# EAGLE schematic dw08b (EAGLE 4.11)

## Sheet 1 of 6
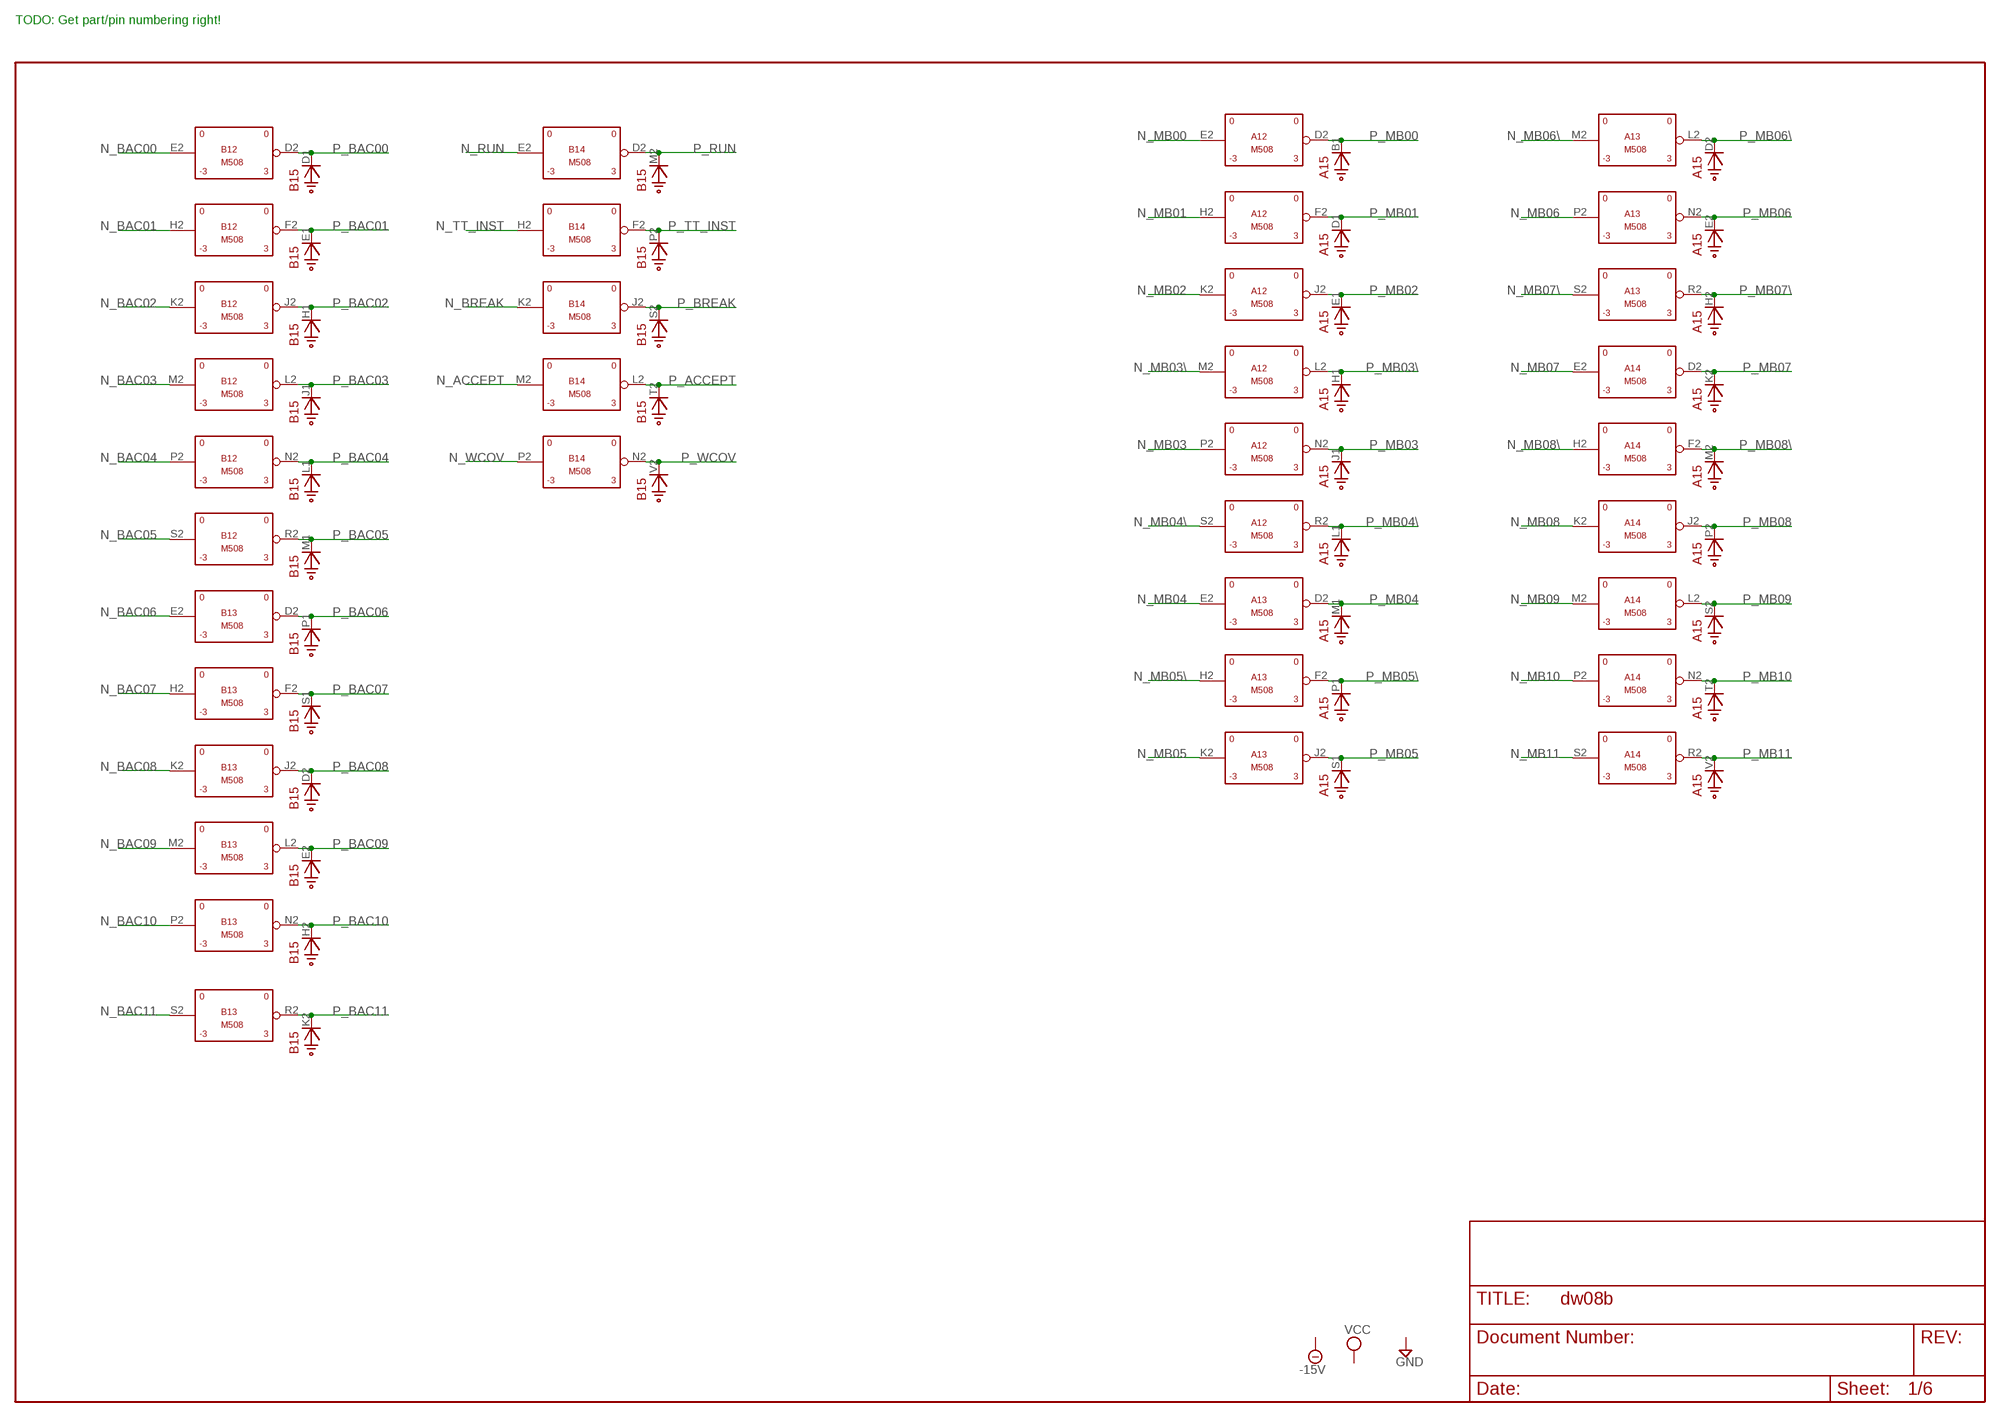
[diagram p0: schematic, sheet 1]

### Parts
A12  M508  [H807]
A13  M508  [H807]
A14  M508  [H807]
A15  M906  [H807]
B12  M508  [H807]
B13  M508  [H807]
B14  M508  [H807]
B15  M906  [H807]

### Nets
N_ACCEPT: B14.M2(IN) ; also sheet 5
N_BAC00: B12.E2(IN) ; also sheet 5
N_BAC01: B12.H2(IN) ; also sheet 5
N_BAC02: B12.K2(IN) ; also sheet 5
N_BAC03: B12.M2(IN) ; also sheet 5
N_BAC04: B12.P2(IN) ; also sheet 5
N_BAC05: B12.S2(IN) ; also sheet 5
N_BAC06: B13.E2(IN) ; also sheet 5
N_BAC07: B13.H2(IN) ; also sheet 5
N_BAC08: B13.K2(IN) ; also sheet 5
N_BAC09: B13.M2(IN) ; also sheet 5
N_BAC10: B13.P2(IN) ; also sheet 5
N_BAC11: B13.S2(IN) ; also sheet 5
N_BREAK: B14.K2(IN) ; also sheet 5
N_MB00: A12.E2(IN) ; also sheet 5
N_MB01: A12.H2(IN) ; also sheet 5
N_MB02: A12.K2(IN) ; also sheet 5
N_MB03: A12.P2(IN) ; also sheet 5
N_MB03\: A12.M2(IN) ; also sheet 5
N_MB04: A13.E2(IN) ; also sheet 5
N_MB04\: A12.S2(IN) ; also sheet 5
N_MB05: A13.K2(IN) ; also sheet 5
N_MB05\: A13.H2(IN) ; also sheet 5
N_MB06: A13.P2(IN) ; also sheet 5
N_MB06\: A13.M2(IN) ; also sheet 5
N_MB07: A14.E2(IN) ; also sheet 5
N_MB07\: A13.S2(IN) ; also sheet 5
N_MB08: A14.K2(IN) ; also sheet 5
N_MB08\: A14.H2(IN) ; also sheet 5
N_MB09: A14.M2(IN) ; also sheet 5
N_MB10: A14.P2(IN) ; also sheet 5
N_MB11: A14.S2(IN) ; also sheet 5
N_RUN: B14.E2(IN) ; also sheet 5
N_TT_INST: B14.H2(IN) ; also sheet 5
N_WCOV: B14.P2(IN) ; also sheet 5
P_ACCEPT: B14.L2(OUT) B15.T2(CATHODE) ; also sheet 6
P_BAC00: B12.D2(OUT) B15.D1(CATHODE) ; also sheet 6
P_BAC01: B12.F2(OUT) B15.E1(CATHODE) ; also sheet 6
P_BAC02: B12.J2(OUT) B15.H1(CATHODE) ; also sheet 6
P_BAC03: B12.L2(OUT) B15.J1(CATHODE) ; also sheet 6
P_BAC04: B12.N2(OUT) B15.L1(CATHODE) ; also sheet 6
P_BAC05: B12.R2(OUT) B15.M1(CATHODE) ; also sheet 6
P_BAC06: B13.D2(OUT) B15.P1(CATHODE) ; also sheet 6
P_BAC07: B13.F2(OUT) B15.S1(CATHODE) ; also sheet 6
P_BAC08: B13.J2(OUT) B15.D2(CATHODE) ; also sheet 6
P_BAC09: B13.L2(OUT) B15.E2(CATHODE) ; also sheet 6
P_BAC10: B13.N2(OUT) B15.H2(CATHODE) ; also sheet 6
P_BAC11: B13.R2(OUT) B15.K2(CATHODE) ; also sheet 6
P_BREAK: B14.J2(OUT) B15.S2(CATHODE) ; also sheet 6
P_MB00: A12.D2(OUT) A15.B1(CATHODE) ; also sheet 6
P_MB01: A12.F2(OUT) A15.D1(CATHODE) ; also sheet 6
P_MB02: A12.J2(OUT) A15.E1(CATHODE) ; also sheet 6
P_MB03: A12.N2(OUT) A15.J1(CATHODE) ; also sheet 6
P_MB03\: A12.L2(OUT) A15.H1(CATHODE) ; also sheet 6
P_MB04: A13.D2(OUT) A15.M1(CATHODE) ; also sheet 6
P_MB04\: A12.R2(OUT) A15.L1(CATHODE) ; also sheet 6
P_MB05: A13.J2(OUT) A15.S1(CATHODE) ; also sheet 6
P_MB05\: A13.F2(OUT) A15.P1(CATHODE) ; also sheet 6
P_MB06: A13.N2(OUT) A15.E2(CATHODE) ; also sheet 6
P_MB06\: A13.L2(OUT) A15.D2(CATHODE) ; also sheet 6
P_MB07: A14.D2(OUT) A15.K2(CATHODE) ; also sheet 6
P_MB07\: A13.R2(OUT) A15.H2(CATHODE) ; also sheet 6
P_MB08: A14.J2(OUT) A15.P2(CATHODE) ; also sheet 6
P_MB08\: A14.F2(OUT) A15.M2(CATHODE) ; also sheet 6
P_MB09: A14.L2(OUT) A15.S2(CATHODE) ; also sheet 6
P_MB10: A14.N2(OUT) A15.T2(CATHODE) ; also sheet 6
P_MB11: A14.R2(OUT) A15.V2(CATHODE) ; also sheet 6
P_RUN: B14.D2(OUT) B15.M2(CATHODE) ; also sheet 6
P_TT_INST: B14.F2(OUT) B15.P2(CATHODE) ; also sheet 6
P_WCOV: B14.N2(OUT) B15.V2(CATHODE) ; also sheet 6
Unconnected: B14.R2(OUT) B14.S2(IN)

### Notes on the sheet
- TODO: Get part/pin numbering right!

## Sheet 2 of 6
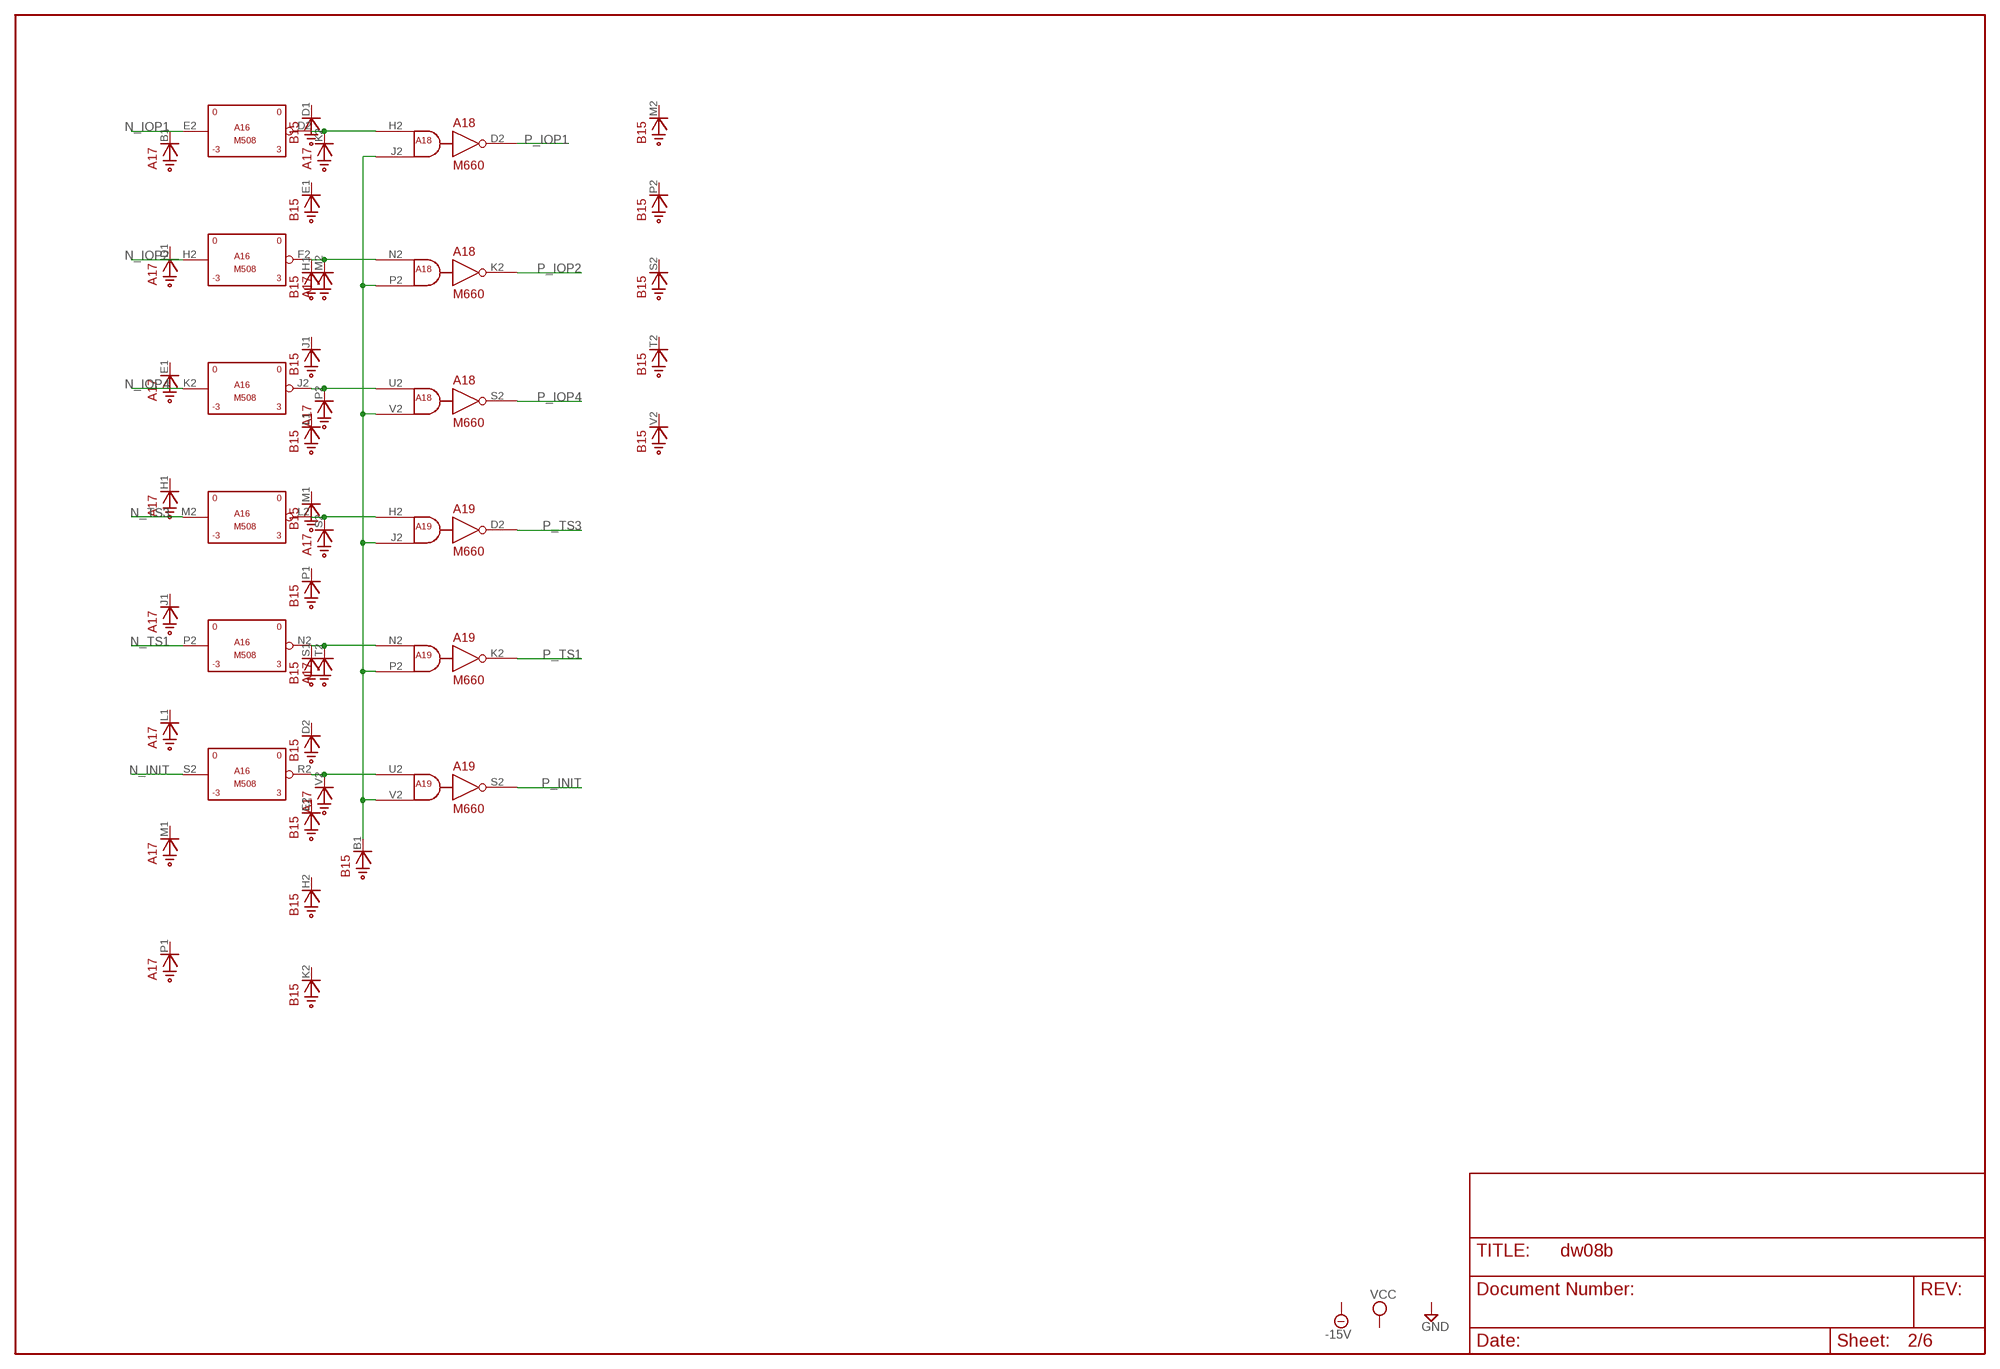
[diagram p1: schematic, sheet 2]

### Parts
A16  M508  [H807]
A17  M906  [H807]
A18  M660  [H807]
A19  M660  [H807]

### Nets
N$1: A16.D2(OUT) A17.K2(CATHODE) A18.H2(IN1)
N$2: A16.F2(OUT) A17.M2(CATHODE) A18.N2(IN1)
N$3: A16.J2(OUT) A17.P2(CATHODE) A18.U2(IN1)
N$4: A16.L2(OUT) A17.S2(CATHODE) A19.H2(IN1)
N$5: A16.N2(OUT) A17.T2(CATHODE) A19.N2(IN1)
N$6: A16.R2(OUT) A17.V2(CATHODE) A19.U2(IN1)
N$7: A18.J2(IN2) A18.P2(IN2) A18.V2(IN2) A19.J2(IN2) A19.P2(IN2) A19.V2(IN2) B15.B1(CATHODE)
N_INIT: A16.S2(IN) ; also sheet 5
N_IOP1: A16.E2(IN) ; also sheet 5
N_IOP2: A16.H2(IN) ; also sheet 5
N_IOP4: A16.K2(IN) ; also sheet 5
N_TS1: A16.P2(IN) ; also sheet 5
N_TS3: A16.M2(IN) ; also sheet 5
P_INIT: A19.S2(OUT) ; also sheet 6
P_IOP1: A18.D2(OUT) ; also sheet 6
P_IOP2: A18.K2(OUT) ; also sheet 6
P_IOP4: A18.S2(OUT) ; also sheet 6
P_TS1: A19.K2(OUT) ; also sheet 6
P_TS3: A19.D2(OUT) ; also sheet 6

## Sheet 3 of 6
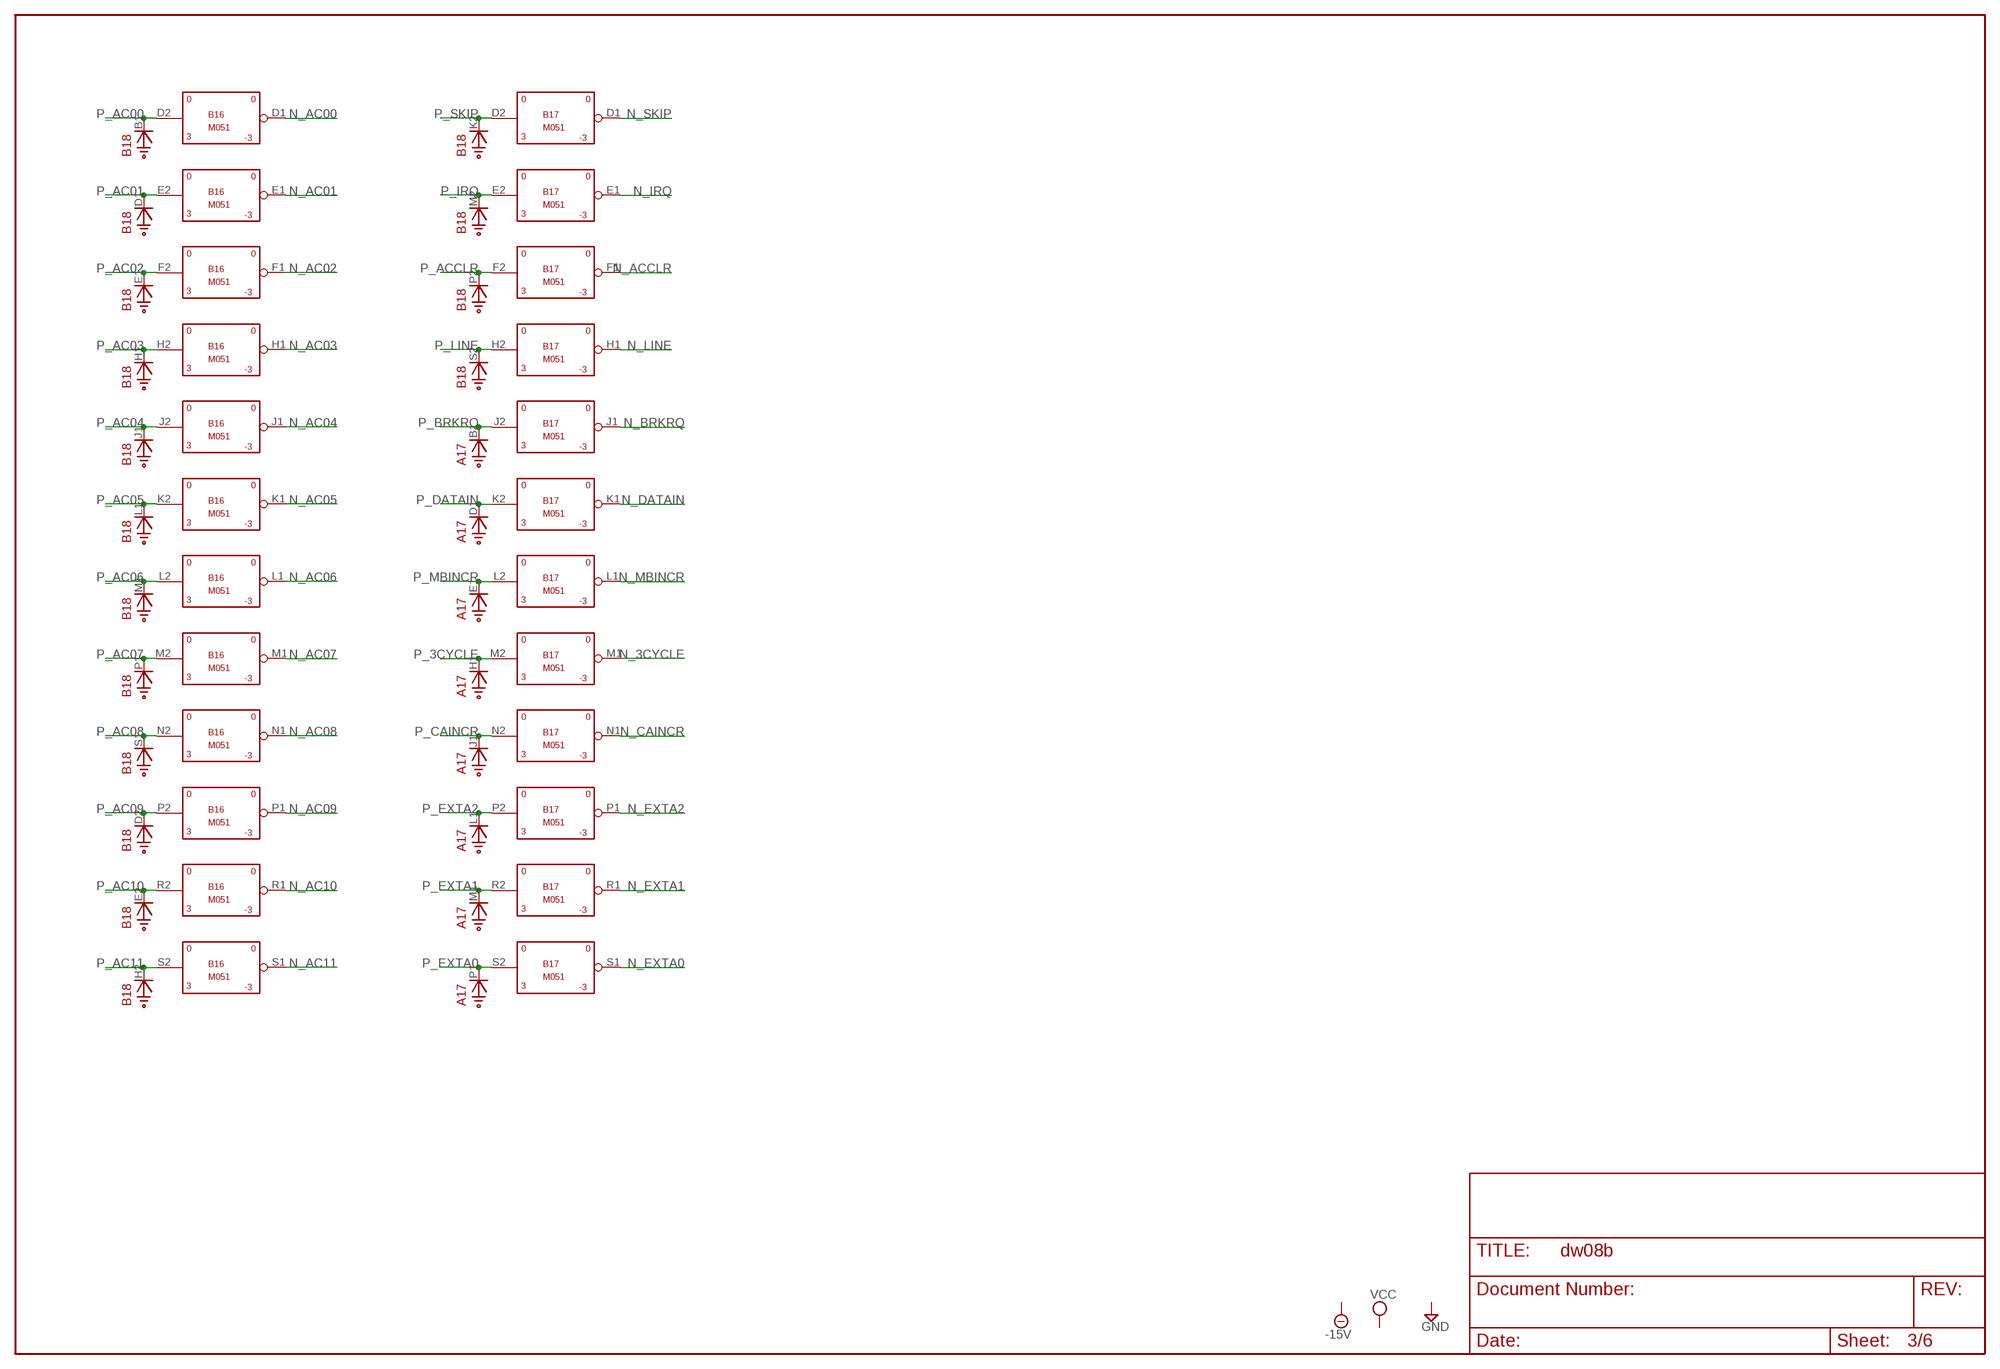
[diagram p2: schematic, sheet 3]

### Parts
B16  M051  [H807]
B17  M051  [H807]
B18  M906  [H807]

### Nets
N_3CYCLE: B17.M1(OUT) ; also sheet 5
N_AC00: B16.D1(OUT) ; also sheet 5
N_AC01: B16.E1(OUT) ; also sheet 5
N_AC02: B16.F1(OUT) ; also sheet 5
N_AC03: B16.H1(OUT) ; also sheet 5
N_AC04: B16.J1(OUT) ; also sheet 5
N_AC05: B16.K1(OUT) ; also sheet 5
N_AC06: B16.L1(OUT) ; also sheet 5
N_AC07: B16.M1(OUT) ; also sheet 5
N_AC08: B16.N1(OUT) ; also sheet 5
N_AC09: B16.P1(OUT) ; also sheet 5
N_AC10: B16.R1(OUT) ; also sheet 5
N_AC11: B16.S1(OUT) ; also sheet 5
N_ACCLR: B17.F1(OUT) ; also sheet 5
N_BRKRQ: B17.J1(OUT) ; also sheet 5
N_CAINCR: B17.N1(OUT) ; also sheet 5
N_DATAIN: B17.K1(OUT) ; also sheet 5
N_EXTA0: B17.S1(OUT) ; also sheet 5
N_EXTA1: B17.R1(OUT) ; also sheet 5
N_EXTA2: B17.P1(OUT) ; also sheet 5
N_IRQ: B17.E1(OUT) ; also sheet 5
N_LINE: B17.H1(OUT) ; also sheet 5
N_MBINCR: B17.L1(OUT) ; also sheet 5
N_SKIP: B17.D1(OUT) ; also sheet 5
P_3CYCLE: A17.H1(CATHODE) B17.M2(IN) ; also sheet 6
P_AC00: B16.D2(IN) B18.B1(CATHODE) ; also sheet 6
P_AC01: B16.E2(IN) B18.D1(CATHODE) ; also sheet 6
P_AC02: B16.F2(IN) B18.E1(CATHODE) ; also sheet 6
P_AC03: B16.H2(IN) B18.H1(CATHODE) ; also sheet 6
P_AC04: B16.J2(IN) B18.J1(CATHODE) ; also sheet 6
P_AC05: B16.K2(IN) B18.L1(CATHODE) ; also sheet 6
P_AC06: B16.L2(IN) B18.M1(CATHODE) ; also sheet 6
P_AC07: B16.M2(IN) B18.P1(CATHODE) ; also sheet 6
P_AC08: B16.N2(IN) B18.S1(CATHODE) ; also sheet 6
P_AC09: B16.P2(IN) B18.D2(CATHODE) ; also sheet 6
P_AC10: B16.R2(IN) B18.E2(CATHODE) ; also sheet 6
P_AC11: B16.S2(IN) B18.H2(CATHODE) ; also sheet 6
P_ACCLR: B17.F2(IN) B18.P2(CATHODE) ; also sheet 6
P_BRKRQ: A17.B1(CATHODE) B17.J2(IN) ; also sheet 6
P_CAINCR: A17.J1(CATHODE) B17.N2(IN) ; also sheet 6
P_DATAIN: A17.D1(CATHODE) B17.K2(IN) ; also sheet 6
P_EXTA0: A17.P1(CATHODE) B17.S2(IN) ; also sheet 6
P_EXTA1: A17.M1(CATHODE) B17.R2(IN) ; also sheet 6
P_EXTA2: A17.L1(CATHODE) B17.P2(IN) ; also sheet 6
P_IRQ: B17.E2(IN) B18.M2(CATHODE) ; also sheet 6
P_LINE: B17.H2(IN) B18.S2(CATHODE) ; also sheet 6
P_MBINCR: A17.E1(CATHODE) B17.L2(IN) ; also sheet 6
P_SKIP: B17.D2(IN) B18.K2(CATHODE) ; also sheet 6

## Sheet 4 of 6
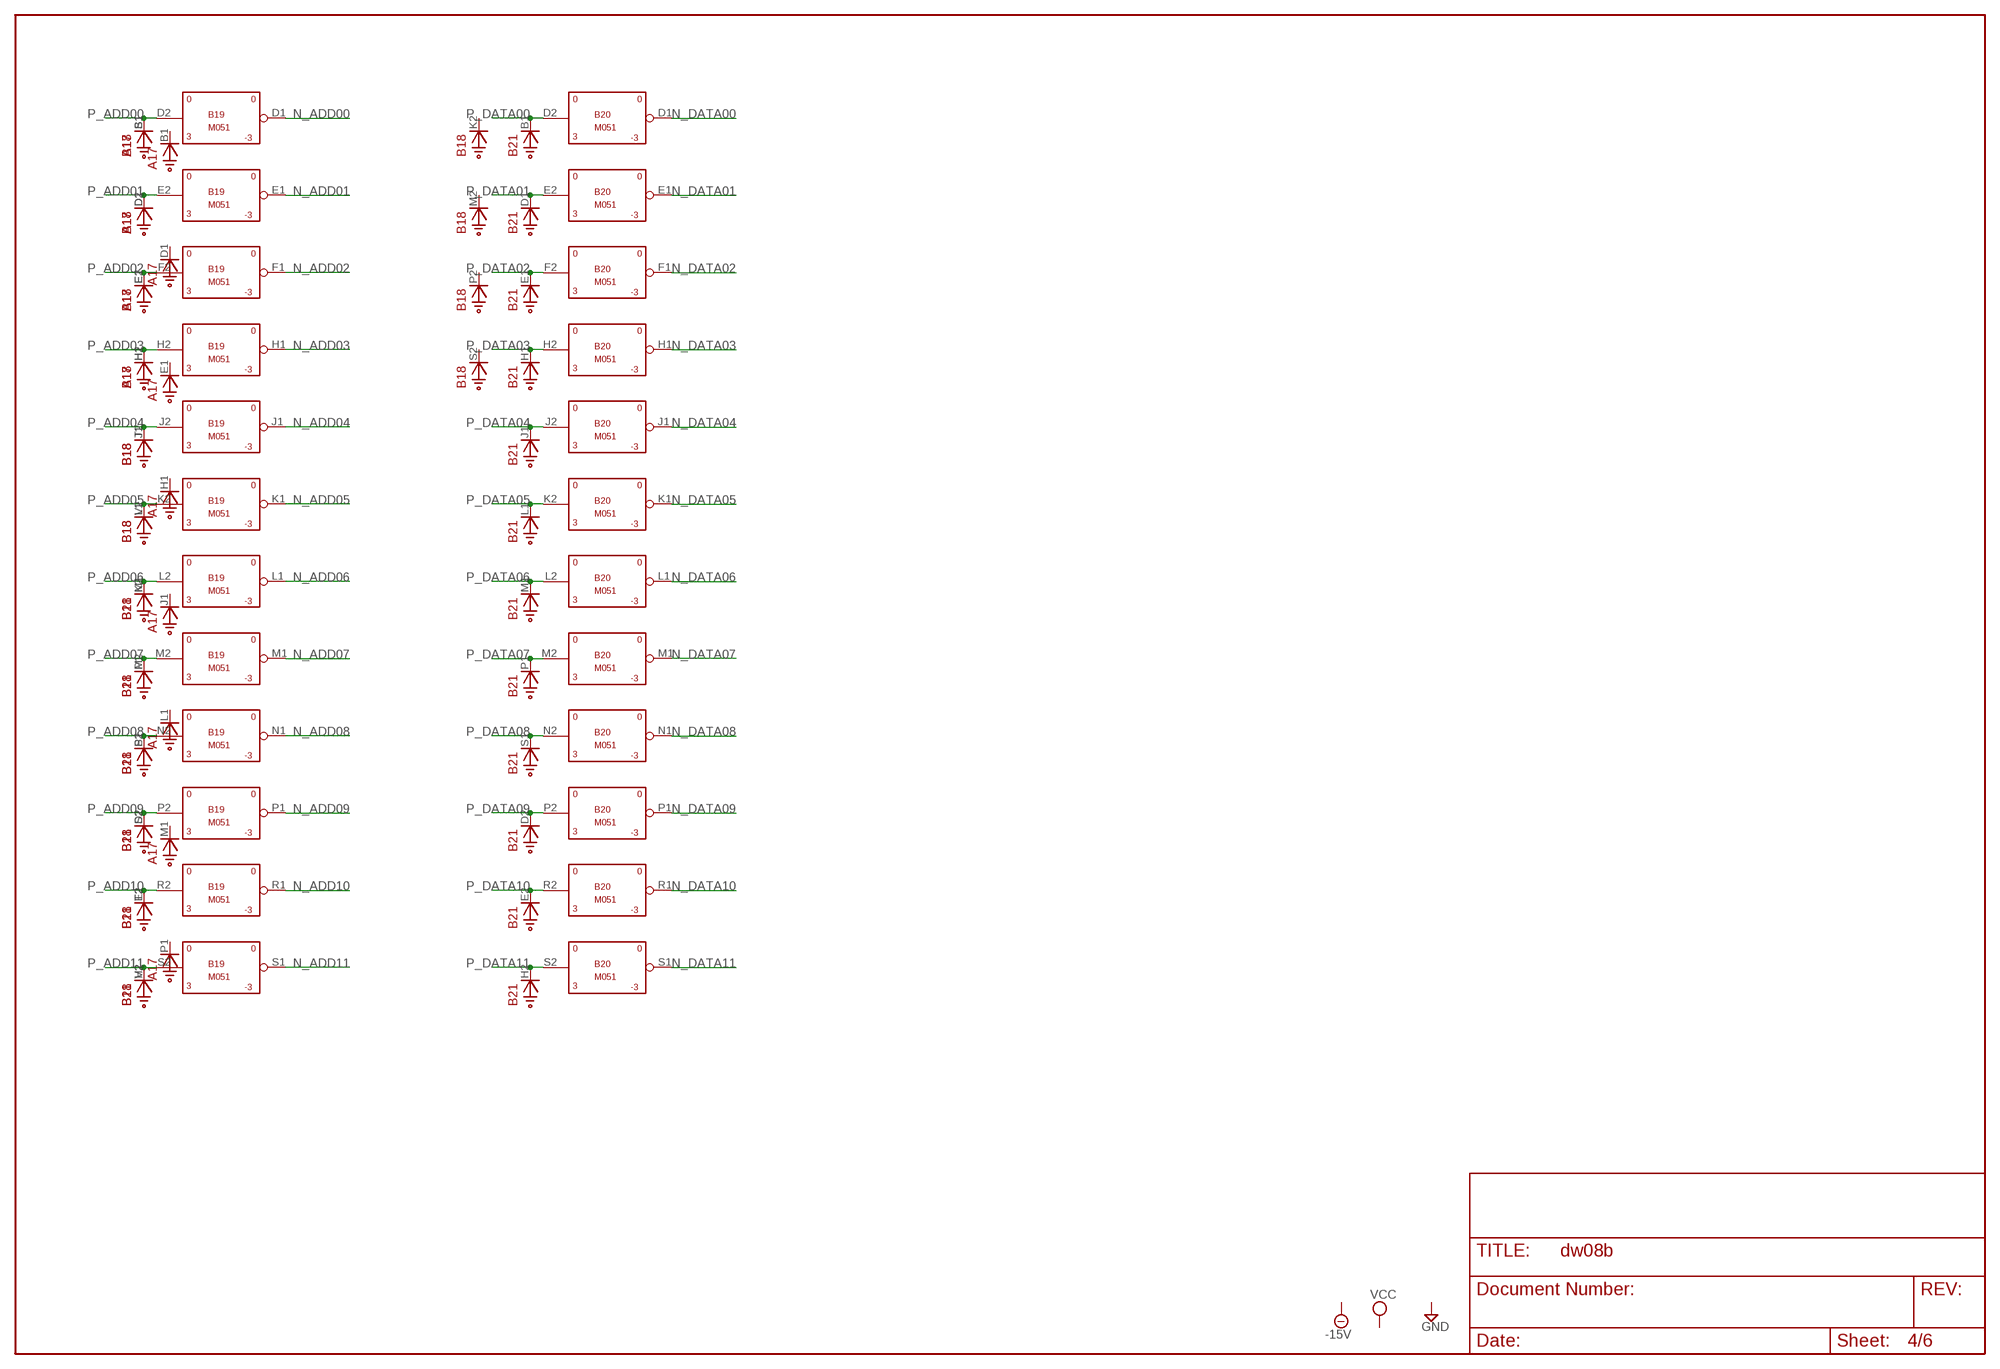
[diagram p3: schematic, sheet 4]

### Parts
B19  M051  [H807]
B20  M051  [H807]
B21  M906  [H807]

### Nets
N_ADD00: B19.D1(OUT) ; also sheet 5
N_ADD01: B19.E1(OUT) ; also sheet 5
N_ADD02: B19.F1(OUT) ; also sheet 5
N_ADD03: B19.H1(OUT) ; also sheet 5
N_ADD04: B19.J1(OUT) ; also sheet 5
N_ADD05: B19.K1(OUT) ; also sheet 5
N_ADD06: B19.L1(OUT) ; also sheet 5
N_ADD07: B19.M1(OUT) ; also sheet 5
N_ADD08: B19.N1(OUT) ; also sheet 5
N_ADD09: B19.P1(OUT) ; also sheet 5
N_ADD10: B19.R1(OUT) ; also sheet 5
N_ADD11: B19.S1(OUT) ; also sheet 5
N_DATA00: B20.D1(OUT) ; also sheet 5
N_DATA01: B20.E1(OUT) ; also sheet 5
N_DATA02: B20.F1(OUT) ; also sheet 5
N_DATA03: B20.H1(OUT) ; also sheet 5
N_DATA04: B20.J1(OUT) ; also sheet 5
N_DATA05: B20.K1(OUT) ; also sheet 5
N_DATA06: B20.L1(OUT) ; also sheet 5
N_DATA07: B20.M1(OUT) ; also sheet 5
N_DATA08: B20.N1(OUT) ; also sheet 5
N_DATA09: B20.P1(OUT) ; also sheet 5
N_DATA10: B20.R1(OUT) ; also sheet 5
N_DATA11: B20.S1(OUT) ; also sheet 5
P_ADD00: A17.S1(CATHODE) B19.D2(IN) ; also sheet 6
P_ADD01: A17.D2(CATHODE) B19.E2(IN) ; also sheet 6
P_ADD02: A17.E2(CATHODE) B19.F2(IN) ; also sheet 6
P_ADD03: A17.H2(CATHODE) B19.H2(IN) ; also sheet 6
P_ADD04: B18.T2(CATHODE) B19.J2(IN) ; also sheet 6
P_ADD05: B18.V2(CATHODE) B19.K2(IN) ; also sheet 6
P_ADD06: B19.L2(IN) B21.K2(CATHODE) ; also sheet 6
P_ADD07: B19.M2(IN) B21.M2(CATHODE) ; also sheet 6
P_ADD08: B19.N2(IN) B21.P2(CATHODE) ; also sheet 6
P_ADD09: B19.P2(IN) B21.S2(CATHODE) ; also sheet 6
P_ADD10: B19.R2(IN) B21.T2(CATHODE) ; also sheet 6
P_ADD11: B19.S2(IN) B21.V2(CATHODE) ; also sheet 6
P_DATA00: B20.D2(IN) B21.B1(CATHODE) ; also sheet 6
P_DATA01: B20.E2(IN) B21.D1(CATHODE) ; also sheet 6
P_DATA02: B20.F2(IN) B21.E1(CATHODE) ; also sheet 6
P_DATA03: B20.H2(IN) B21.H1(CATHODE) ; also sheet 6
P_DATA04: B20.J2(IN) B21.J1(CATHODE) ; also sheet 6
P_DATA05: B20.K2(IN) B21.L1(CATHODE) ; also sheet 6
P_DATA06: B20.L2(IN) B21.M1(CATHODE) ; also sheet 6
P_DATA07: B20.M2(IN) B21.P1(CATHODE) ; also sheet 6
P_DATA08: B20.N2(IN) B21.S1(CATHODE) ; also sheet 6
P_DATA09: B20.P2(IN) B21.D2(CATHODE) ; also sheet 6
P_DATA10: B20.R2(IN) B21.E2(CATHODE) ; also sheet 6
P_DATA11: B20.S2(IN) B21.H2(CATHODE) ; also sheet 6

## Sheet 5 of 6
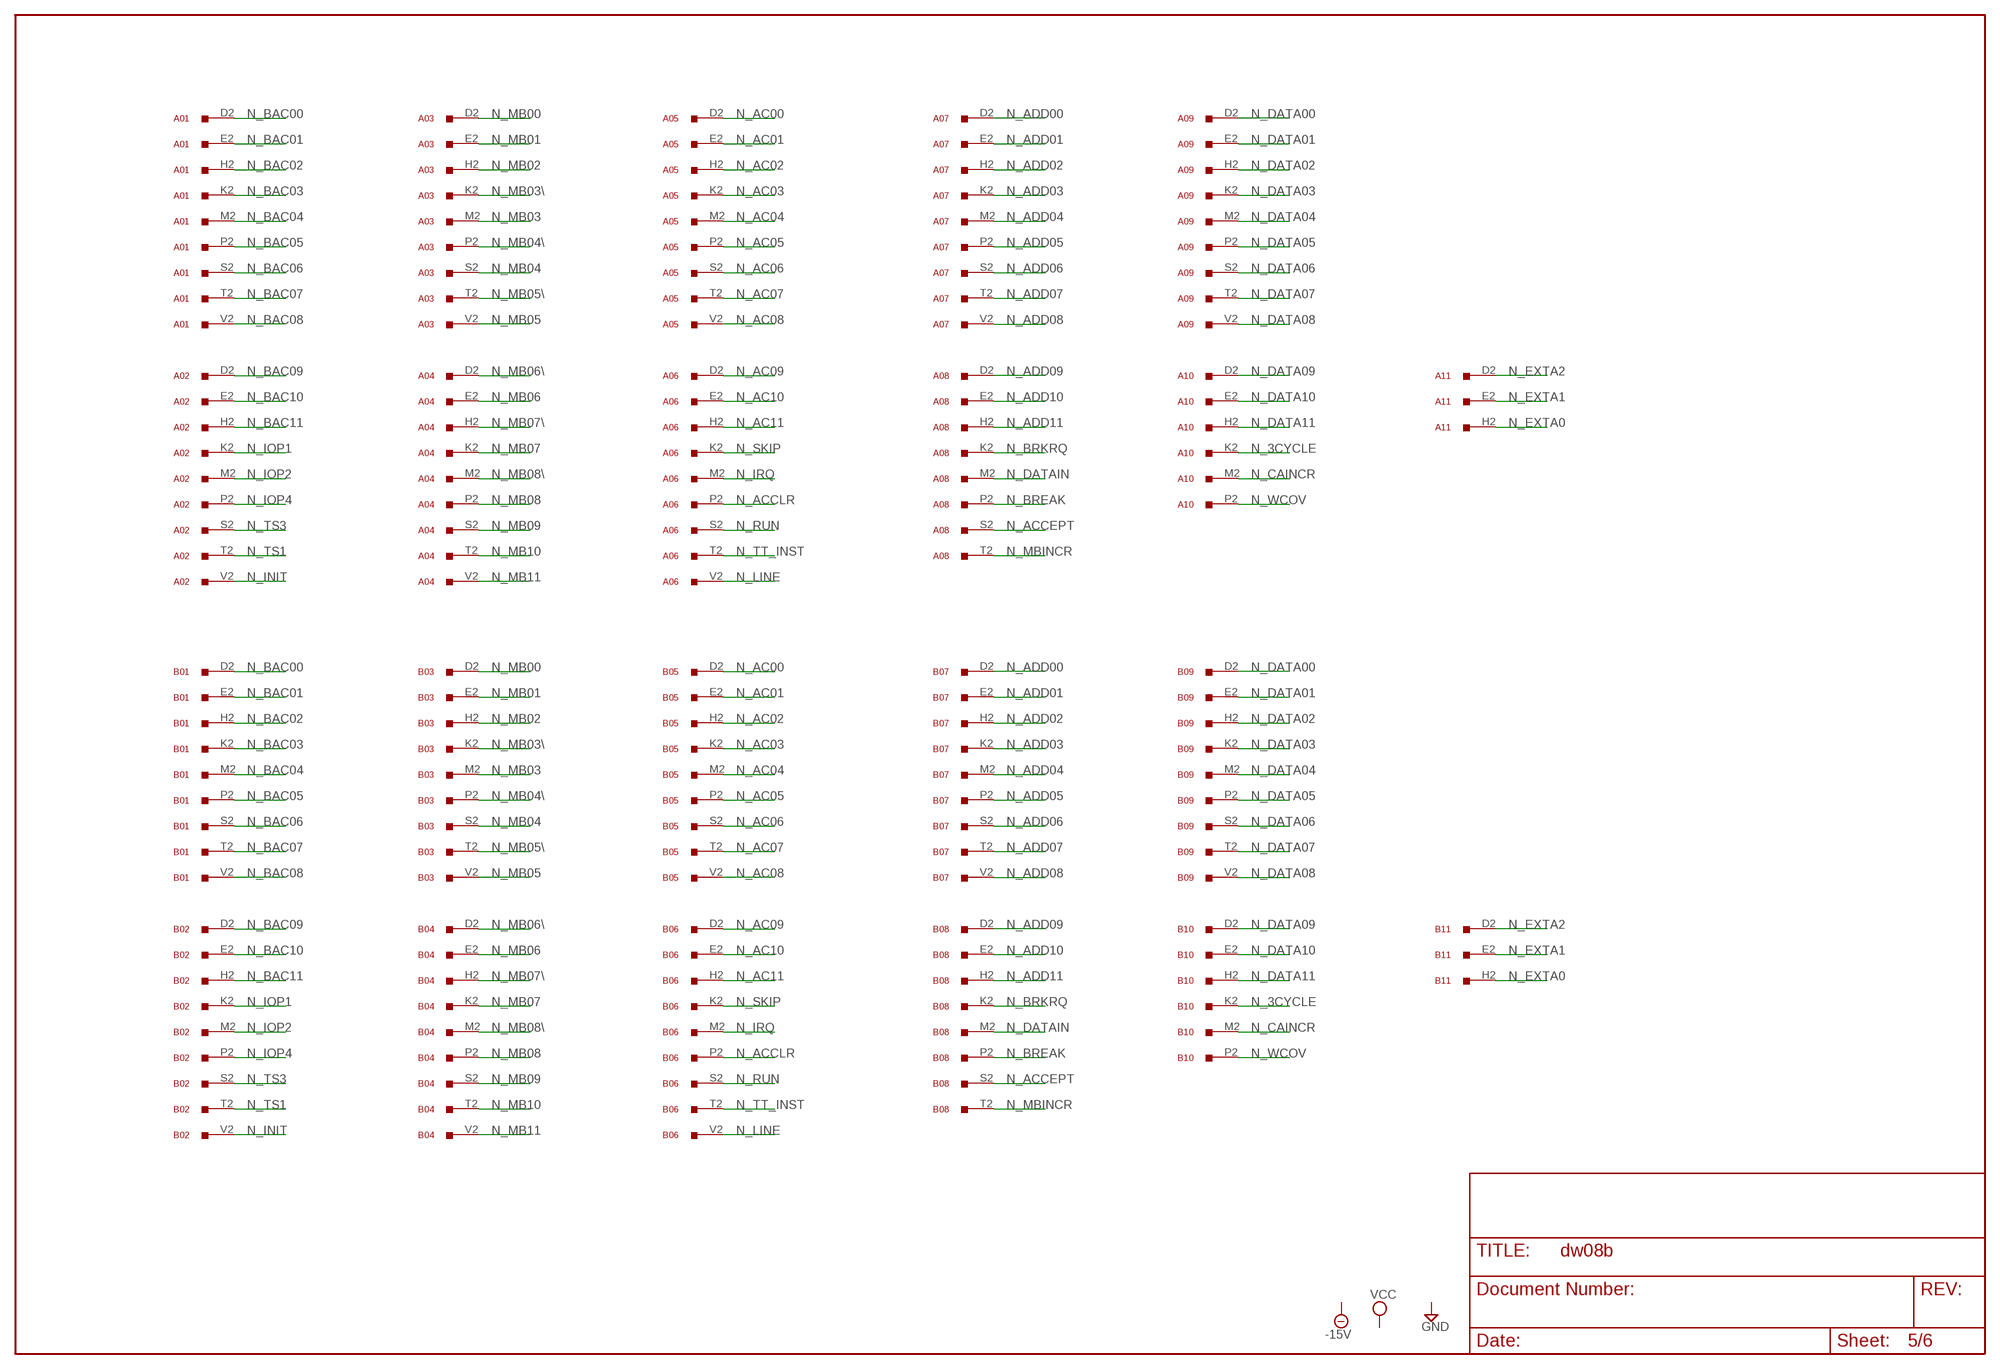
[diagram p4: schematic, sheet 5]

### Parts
A01  W011  [H807]
A02  W011  [H807]
A03  W011  [H807]
A04  W011  [H807]
A05  W011  [H807]
A06  W011  [H807]
A07  W011  [H807]
A08  W011  [H807]
A09  W011  [H807]
A10  W011  [H807]
A11  W011  [H807]
B01  W011  [H807]
B02  W011  [H807]
B03  W011  [H807]
B04  W011  [H807]
B05  W011  [H807]
B06  W011  [H807]
B07  W011  [H807]
B08  W011  [H807]
B09  W011  [H807]
B10  W011  [H807]
B11  W011  [H807]

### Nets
N_3CYCLE: A10.K2 B10.K2 ; also sheet 3
N_AC00: A05.D2 B05.D2 ; also sheet 3
N_AC01: A05.E2 B05.E2 ; also sheet 3
N_AC02: A05.H2 B05.H2 ; also sheet 3
N_AC03: A05.K2 B05.K2 ; also sheet 3
N_AC04: A05.M2 B05.M2 ; also sheet 3
N_AC05: A05.P2 B05.P2 ; also sheet 3
N_AC06: A05.S2 B05.S2 ; also sheet 3
N_AC07: A05.T2 B05.T2 ; also sheet 3
N_AC08: A05.V2 B05.V2 ; also sheet 3
N_AC09: A06.D2 B06.D2 ; also sheet 3
N_AC10: A06.E2 B06.E2 ; also sheet 3
N_AC11: A06.H2 B06.H2 ; also sheet 3
N_ACCEPT: A08.S2 B08.S2 ; also sheet 1
N_ACCLR: A06.P2 B06.P2 ; also sheet 3
N_ADD00: A07.D2 B07.D2 ; also sheet 4
N_ADD01: A07.E2 B07.E2 ; also sheet 4
N_ADD02: A07.H2 B07.H2 ; also sheet 4
N_ADD03: A07.K2 B07.K2 ; also sheet 4
N_ADD04: A07.M2 B07.M2 ; also sheet 4
N_ADD05: A07.P2 B07.P2 ; also sheet 4
N_ADD06: A07.S2 B07.S2 ; also sheet 4
N_ADD07: A07.T2 B07.T2 ; also sheet 4
N_ADD08: A07.V2 B07.V2 ; also sheet 4
N_ADD09: A08.D2 B08.D2 ; also sheet 4
N_ADD10: A08.E2 B08.E2 ; also sheet 4
N_ADD11: A08.H2 B08.H2 ; also sheet 4
N_BAC00: A01.D2 B01.D2 ; also sheet 1
N_BAC01: A01.E2 B01.E2 ; also sheet 1
N_BAC02: A01.H2 B01.H2 ; also sheet 1
N_BAC03: A01.K2 B01.K2 ; also sheet 1
N_BAC04: A01.M2 B01.M2 ; also sheet 1
N_BAC05: A01.P2 B01.P2 ; also sheet 1
N_BAC06: A01.S2 B01.S2 ; also sheet 1
N_BAC07: A01.T2 B01.T2 ; also sheet 1
N_BAC08: A01.V2 B01.V2 ; also sheet 1
N_BAC09: A02.D2 B02.D2 ; also sheet 1
N_BAC10: A02.E2 B02.E2 ; also sheet 1
N_BAC11: A02.H2 B02.H2 ; also sheet 1
N_BREAK: A08.P2 B08.P2 ; also sheet 1
N_BRKRQ: A08.K2 B08.K2 ; also sheet 3
N_CAINCR: A10.M2 B10.M2 ; also sheet 3
N_DATA00: A09.D2 B09.D2 ; also sheet 4
N_DATA01: A09.E2 B09.E2 ; also sheet 4
N_DATA02: A09.H2 B09.H2 ; also sheet 4
N_DATA03: A09.K2 B09.K2 ; also sheet 4
N_DATA04: A09.M2 B09.M2 ; also sheet 4
N_DATA05: A09.P2 B09.P2 ; also sheet 4
N_DATA06: A09.S2 B09.S2 ; also sheet 4
N_DATA07: A09.T2 B09.T2 ; also sheet 4
N_DATA08: A09.V2 B09.V2 ; also sheet 4
N_DATA09: A10.D2 B10.D2 ; also sheet 4
N_DATA10: A10.E2 B10.E2 ; also sheet 4
N_DATA11: A10.H2 B10.H2 ; also sheet 4
N_DATAIN: A08.M2 B08.M2 ; also sheet 3
N_EXTA0: A11.H2 B11.H2 ; also sheet 3
N_EXTA1: A11.E2 B11.E2 ; also sheet 3
N_EXTA2: A11.D2 B11.D2 ; also sheet 3
N_INIT: A02.V2 B02.V2 ; also sheet 2
N_IOP1: A02.K2 B02.K2 ; also sheet 2
N_IOP2: A02.M2 B02.M2 ; also sheet 2
N_IOP4: A02.P2 B02.P2 ; also sheet 2
N_IRQ: A06.M2 B06.M2 ; also sheet 3
N_LINE: A06.V2 B06.V2 ; also sheet 3
N_MB00: A03.D2 B03.D2 ; also sheet 1
N_MB01: A03.E2 B03.E2 ; also sheet 1
N_MB02: A03.H2 B03.H2 ; also sheet 1
N_MB03: A03.M2 B03.M2 ; also sheet 1
N_MB03\: A03.K2 B03.K2 ; also sheet 1
N_MB04: A03.S2 B03.S2 ; also sheet 1
N_MB04\: A03.P2 B03.P2 ; also sheet 1
N_MB05: A03.V2 B03.V2 ; also sheet 1
N_MB05\: A03.T2 B03.T2 ; also sheet 1
N_MB06: A04.E2 B04.E2 ; also sheet 1
N_MB06\: A04.D2 B04.D2 ; also sheet 1
N_MB07: A04.K2 B04.K2 ; also sheet 1
N_MB07\: A04.H2 B04.H2 ; also sheet 1
N_MB08: A04.P2 B04.P2 ; also sheet 1
N_MB08\: A04.M2 B04.M2 ; also sheet 1
N_MB09: A04.S2 B04.S2 ; also sheet 1
N_MB10: A04.T2 B04.T2 ; also sheet 1
N_MB11: A04.V2 B04.V2 ; also sheet 1
N_MBINCR: A08.T2 B08.T2 ; also sheet 3
N_RUN: A06.S2 B06.S2 ; also sheet 1
N_SKIP: A06.K2 B06.K2 ; also sheet 3
N_TS1: A02.T2 B02.T2 ; also sheet 2
N_TS3: A02.S2 B02.S2 ; also sheet 2
N_TT_INST: A06.T2 B06.T2 ; also sheet 1
N_WCOV: A10.P2 B10.P2 ; also sheet 1
Unconnected: A08.V2 A10.S2 A10.T2 A10.V2 A11.K2 A11.M2 A11.P2 A11.S2 A11.T2 A11.V2 B08.V2 B10.S2 B10.T2 B10.V2 B11.K2 B11.M2 B11.P2 B11.S2 B11.T2 B11.V2

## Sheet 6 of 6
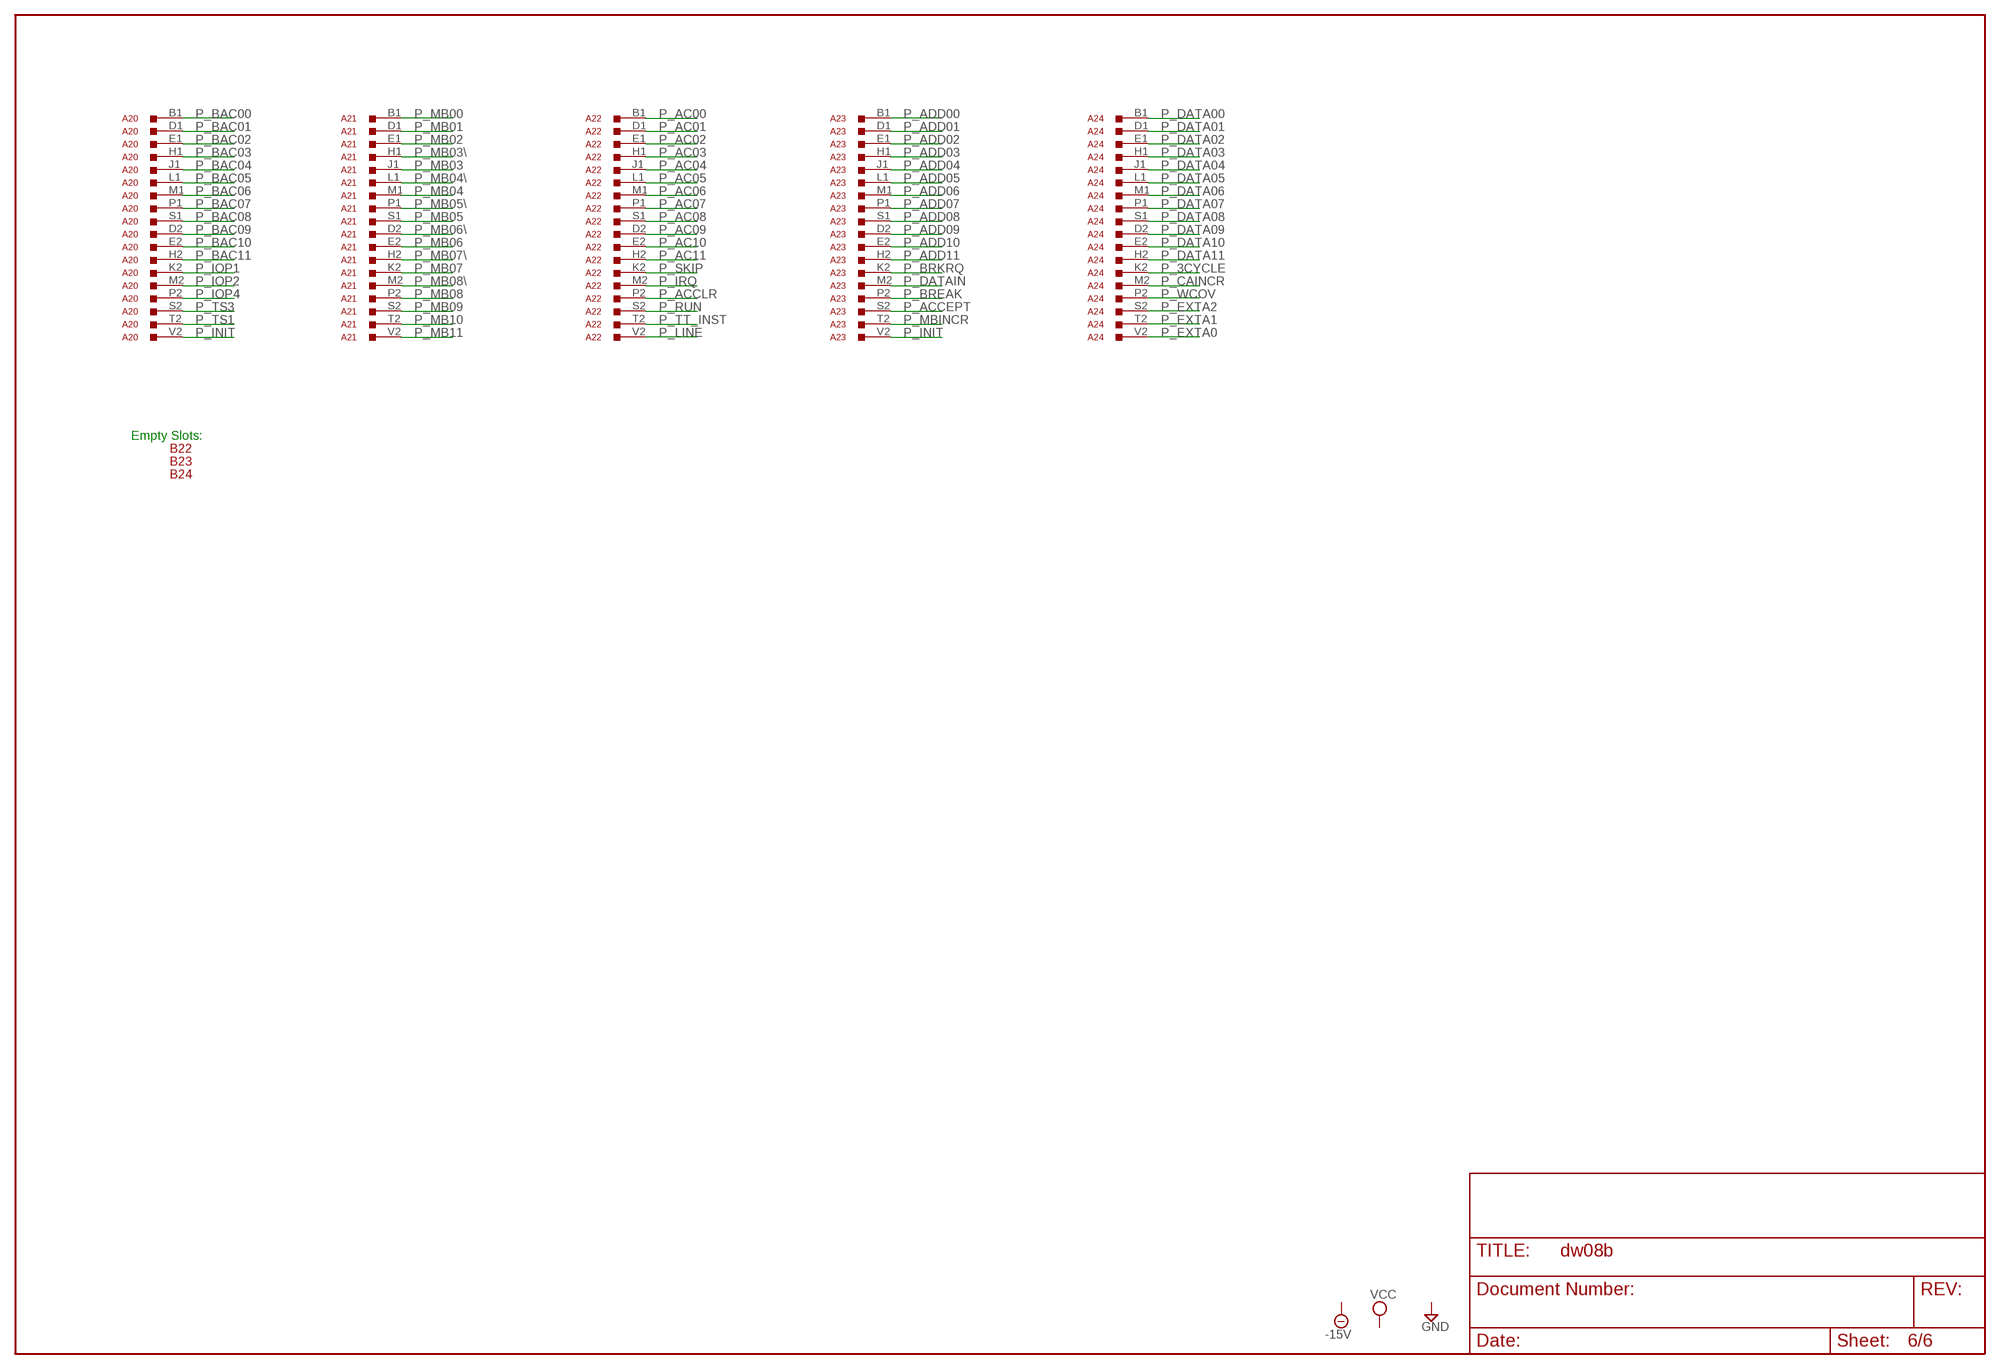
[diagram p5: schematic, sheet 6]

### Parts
A20  M903  [H807]
A21  M903  [H807]
A22  M903  [H807]
A23  M903  [H807]
A24  M903  [H807]
B22  H807  [H807]
B23  H807  [H807]
B24  H807  [H807]

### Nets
P_3CYCLE: A24.K2 ; also sheet 3
P_AC00: A22.B1 ; also sheet 3
P_AC01: A22.D1 ; also sheet 3
P_AC02: A22.E1 ; also sheet 3
P_AC03: A22.H1 ; also sheet 3
P_AC04: A22.J1 ; also sheet 3
P_AC05: A22.L1 ; also sheet 3
P_AC06: A22.M1 ; also sheet 3
P_AC07: A22.P1 ; also sheet 3
P_AC08: A22.S1 ; also sheet 3
P_AC09: A22.D2 ; also sheet 3
P_AC10: A22.E2 ; also sheet 3
P_AC11: A22.H2 ; also sheet 3
P_ACCEPT: A23.S2 ; also sheet 1
P_ACCLR: A22.P2 ; also sheet 3
P_ADD00: A23.B1 ; also sheet 4
P_ADD01: A23.D1 ; also sheet 4
P_ADD02: A23.E1 ; also sheet 4
P_ADD03: A23.H1 ; also sheet 4
P_ADD04: A23.J1 ; also sheet 4
P_ADD05: A23.L1 ; also sheet 4
P_ADD06: A23.M1 ; also sheet 4
P_ADD07: A23.P1 ; also sheet 4
P_ADD08: A23.S1 ; also sheet 4
P_ADD09: A23.D2 ; also sheet 4
P_ADD10: A23.E2 ; also sheet 4
P_ADD11: A23.H2 ; also sheet 4
P_BAC00: A20.B1 ; also sheet 1
P_BAC01: A20.D1 ; also sheet 1
P_BAC02: A20.E1 ; also sheet 1
P_BAC03: A20.H1 ; also sheet 1
P_BAC04: A20.J1 ; also sheet 1
P_BAC05: A20.L1 ; also sheet 1
P_BAC06: A20.M1 ; also sheet 1
P_BAC07: A20.P1 ; also sheet 1
P_BAC08: A20.S1 ; also sheet 1
P_BAC09: A20.D2 ; also sheet 1
P_BAC10: A20.E2 ; also sheet 1
P_BAC11: A20.H2 ; also sheet 1
P_BREAK: A23.P2 ; also sheet 1
P_BRKRQ: A23.K2 ; also sheet 3
P_CAINCR: A24.M2 ; also sheet 3
P_DATA00: A24.B1 ; also sheet 4
P_DATA01: A24.D1 ; also sheet 4
P_DATA02: A24.E1 ; also sheet 4
P_DATA03: A24.H1 ; also sheet 4
P_DATA04: A24.J1 ; also sheet 4
P_DATA05: A24.L1 ; also sheet 4
P_DATA06: A24.M1 ; also sheet 4
P_DATA07: A24.P1 ; also sheet 4
P_DATA08: A24.S1 ; also sheet 4
P_DATA09: A24.D2 ; also sheet 4
P_DATA10: A24.E2 ; also sheet 4
P_DATA11: A24.H2 ; also sheet 4
P_DATAIN: A23.M2 ; also sheet 3
P_EXTA0: A24.V2 ; also sheet 3
P_EXTA1: A24.T2 ; also sheet 3
P_EXTA2: A24.S2 ; also sheet 3
P_INIT: A20.V2 A23.V2 ; also sheet 2
P_IOP1: A20.K2 ; also sheet 2
P_IOP2: A20.M2 ; also sheet 2
P_IOP4: A20.P2 ; also sheet 2
P_IRQ: A22.M2 ; also sheet 3
P_LINE: A22.V2 ; also sheet 3
P_MB00: A21.B1 ; also sheet 1
P_MB01: A21.D1 ; also sheet 1
P_MB02: A21.E1 ; also sheet 1
P_MB03: A21.J1 ; also sheet 1
P_MB03\: A21.H1 ; also sheet 1
P_MB04: A21.M1 ; also sheet 1
P_MB04\: A21.L1 ; also sheet 1
P_MB05: A21.S1 ; also sheet 1
P_MB05\: A21.P1 ; also sheet 1
P_MB06: A21.E2 ; also sheet 1
P_MB06\: A21.D2 ; also sheet 1
P_MB07: A21.K2 ; also sheet 1
P_MB07\: A21.H2 ; also sheet 1
P_MB08: A21.P2 ; also sheet 1
P_MB08\: A21.M2 ; also sheet 1
P_MB09: A21.S2 ; also sheet 1
P_MB10: A21.T2 ; also sheet 1
P_MB11: A21.V2 ; also sheet 1
P_MBINCR: A23.T2 ; also sheet 3
P_RUN: A22.S2 ; also sheet 1
P_SKIP: A22.K2 ; also sheet 3
P_TS1: A20.T2 ; also sheet 2
P_TS3: A20.S2 ; also sheet 2
P_TT_INST: A22.T2 ; also sheet 1
P_WCOV: A24.P2 ; also sheet 1

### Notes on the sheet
- Empty Slots:

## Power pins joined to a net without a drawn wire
-15V: A12.B2(-15V) A13.B2(-15V) A14.B2(-15V) A16.B2(-15V) B12.B2(-15V) B13.B2(-15V) B14.B2(-15V) B16.B2(-15V) B17.B2(-15V) B19.B2(-15V) B20.B2(-15V)
GND: A01.C2 A01.F2 A01.J2 A01.L2 A01.N2 A01.R2 A01.U2 A02.C2 A02.F2 A02.J2 A02.L2 A02.N2 A02.R2 A02.U2 A03.C2 A03.F2 A03.J2 A03.L2 A03.N2 A03.R2 A03.U2 A04.C2 A04.F2 A04.J2 A04.L2 A04.N2 A04.R2 A04.U2 A05.C2 A05.F2 A05.J2 A05.L2 A05.N2 A05.R2 A05.U2 A06.C2 A06.F2 A06.J2 A06.L2 A06.N2 A06.R2 A06.U2 A07.C2 A07.F2 A07.J2 A07.L2 A07.N2 A07.R2 A07.U2 A08.C2 A08.F2 A08.J2 A08.L2 A08.N2 A08.R2 A08.U2 A09.C2 A09.F2 A09.J2 A09.L2 A09.N2 A09.R2 A09.U2 A10.C2 A10.F2 A10.J2 A10.L2 A10.N2 A10.R2 A10.U2 A11.C2 A11.F2 A11.J2 A11.L2 A11.N2 A11.R2 A11.U2 A12.C2(GND) A13.C2(GND) A14.C2(GND) A15.A1(GND) A15.C1(GND) A15.C2(GND) A15.F1(GND) A15.F2(GND) A15.J2(GND) A15.K1(GND) A15.L2(GND) A15.N1(GND) A15.N2(GND) A15.R1(GND) A15.R2(GND) A15.T1(GND) A15.U2(GND) A16.C2(GND) A17.A1(GND) A17.C1(GND) A17.C2(GND) A17.F1(GND) A17.F2(GND) A17.J2(GND) A17.K1(GND) A17.L2(GND) A17.N1(GND) A17.N2(GND) A17.R1(GND) A17.R2(GND) A17.T1(GND) A17.U2(GND) A18.C2(GND) A19.C2(GND) A20.A1 A20.C1 A20.C2 A20.F1 A20.F2 A20.J2 A20.K1 A20.L2 A20.N1 A20.N2 A20.R1 A20.R2 A20.T1 A20.U2 A21.A1 A21.C1 A21.C2 A21.F1 A21.F2 A21.J2 A21.K1 A21.L2 A21.N1 A21.N2 A21.R1 A21.R2 A21.T1 A21.U2 A22.A1 A22.C1 A22.C2 A22.F1 A22.F2 A22.J2 A22.K1 A22.L2 A22.N1 A22.N2 A22.R1 A22.R2 A22.T1 A22.U2 A23.A1 A23.C1 A23.C2 A23.F1 A23.F2 A23.J2 A23.K1 A23.L2 A23.N1 A23.N2 A23.R1 A23.R2 A23.T1 A23.U2 A24.A1 A24.C1 A24.C2 A24.F1 A24.F2 A24.J2 A24.K1 A24.L2 A24.N1 A24.N2 A24.R1 A24.R2 A24.T1 A24.U2 B01.C2 B01.F2 B01.J2 B01.L2 B01.N2 B01.R2 B01.U2 B02.C2 B02.F2 B02.J2 B02.L2 B02.N2 B02.R2 B02.U2 B03.C2 B03.F2 B03.J2 B03.L2 B03.N2 B03.R2 B03.U2 B04.C2 B04.F2 B04.J2 B04.L2 B04.N2 B04.R2 B04.U2 B05.C2 B05.F2 B05.J2 B05.L2 B05.N2 B05.R2 B05.U2 B06.C2 B06.F2 B06.J2 B06.L2 B06.N2 B06.R2 B06.U2 B07.C2 B07.F2 B07.J2 B07.L2 B07.N2 B07.R2 B07.U2 B08.C2 B08.F2 B08.J2 B08.L2 B08.N2 B08.R2 B08.U2 B09.C2 B09.F2 B09.J2 B09.L2 B09.N2 B09.R2 B09.U2 B10.C2 B10.F2 B10.J2 B10.L2 B10.N2 B10.R2 B10.U2 B11.C2 B11.F2 B11.J2 B11.L2 B11.N2 B11.R2 B11.U2 B12.C2(GND) B13.C2(GND) B14.C2(GND) B15.A1(GND) B15.C1(GND) B15.C2(GND) B15.F1(GND) B15.F2(GND) B15.J2(GND) B15.K1(GND) B15.L2(GND) B15.N1(GND) B15.N2(GND) B15.R1(GND) B15.R2(GND) B15.T1(GND) B15.U2(GND) B16.C2(GND) B16.T1(GND) B17.C2(GND) B17.T1(GND) B18.A1(GND) B18.C1(GND) B18.C2(GND) B18.F1(GND) B18.F2(GND) B18.J2(GND) B18.K1(GND) B18.L2(GND) B18.N1(GND) B18.N2(GND) B18.R1(GND) B18.R2(GND) B18.T1(GND) B18.U2(GND) B19.C2(GND) B19.T1(GND) B20.C2(GND) B20.T1(GND) B21.A1(GND) B21.C1(GND) B21.C2(GND) B21.F1(GND) B21.F2(GND) B21.J2(GND) B21.K1(GND) B21.L2(GND) B21.N1(GND) B21.N2(GND) B21.R1(GND) B21.R2(GND) B21.T1(GND) B21.U2(GND)
VCC: A12.A2(VCC) A13.A2(VCC) A14.A2(VCC) A15.A2(VCC) A16.A2(VCC) A17.A2(VCC) A18.A2(VCC) A19.A2(VCC) B12.A2(VCC) B13.A2(VCC) B14.A2(VCC) B15.A2(VCC) B16.A2(VCC) B17.A2(VCC) B18.A2(VCC) B19.A2(VCC) B20.A2(VCC) B21.A2(VCC)

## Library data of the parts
A01-A09 A10 A11 B01-B09 B10 B11 = dec-m:W011: One-sided 9 pin connector/cable with grounds (Negibus).
A12-A14 A16 B12-B14 = dec-m:M508: M508 Negative Bus Converter
A15 A17 B15 B18 B21 = dec-m:M906: M906 Diode Clamp
A18 A19 = dec-m:M660: Positive Level Driver
A20-A24 = dec-m:M903: Two-sided Posibus cable/connector.
B16 B17 B19 B20 = dec-m:M051: M051 Positive Bus Converter
B22-B24 = dec-m:H807: Empty card slot

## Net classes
1 supply: width 1.27 mm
